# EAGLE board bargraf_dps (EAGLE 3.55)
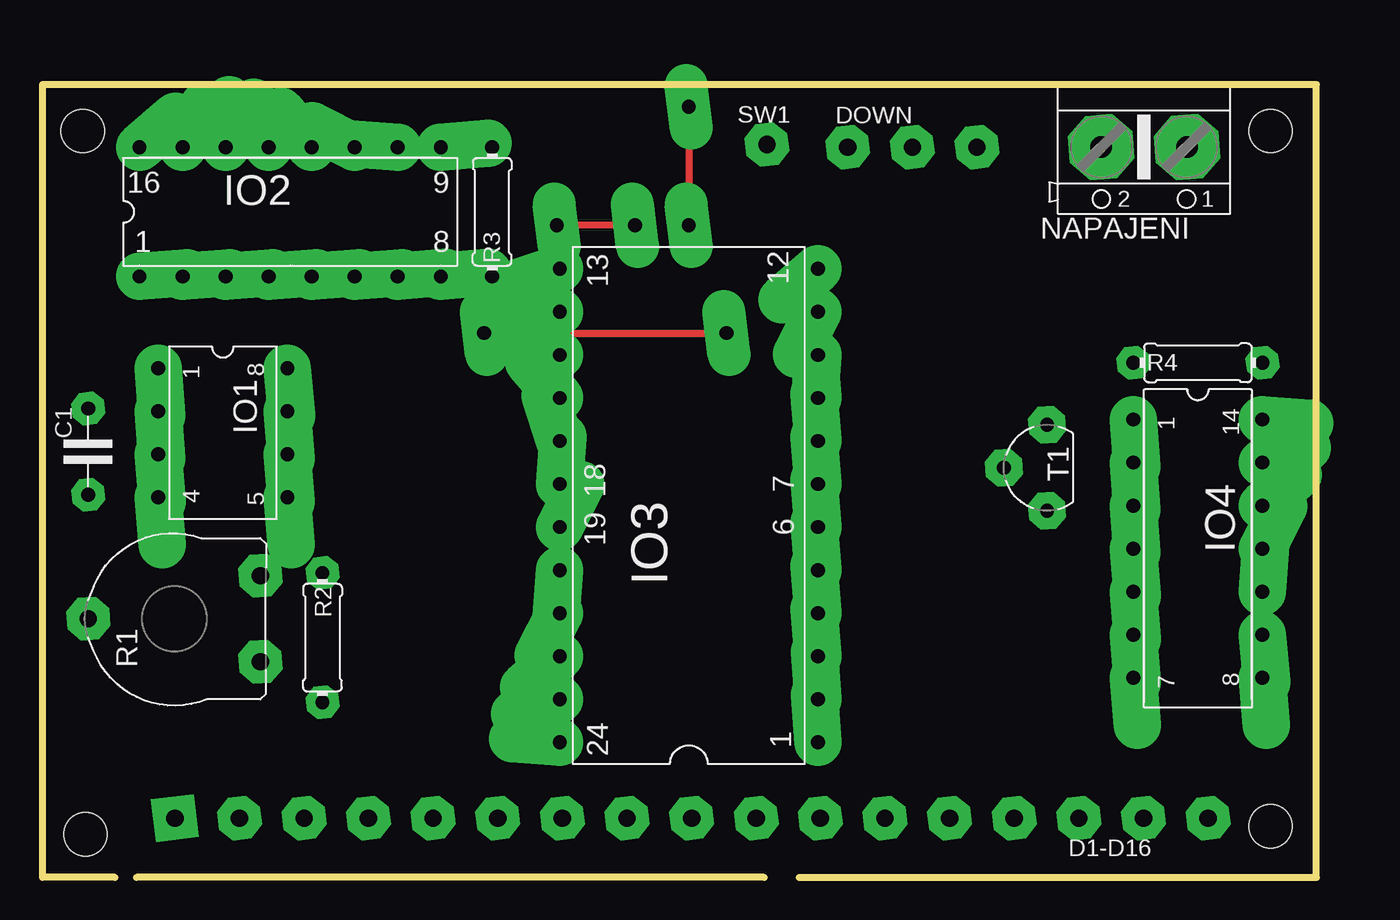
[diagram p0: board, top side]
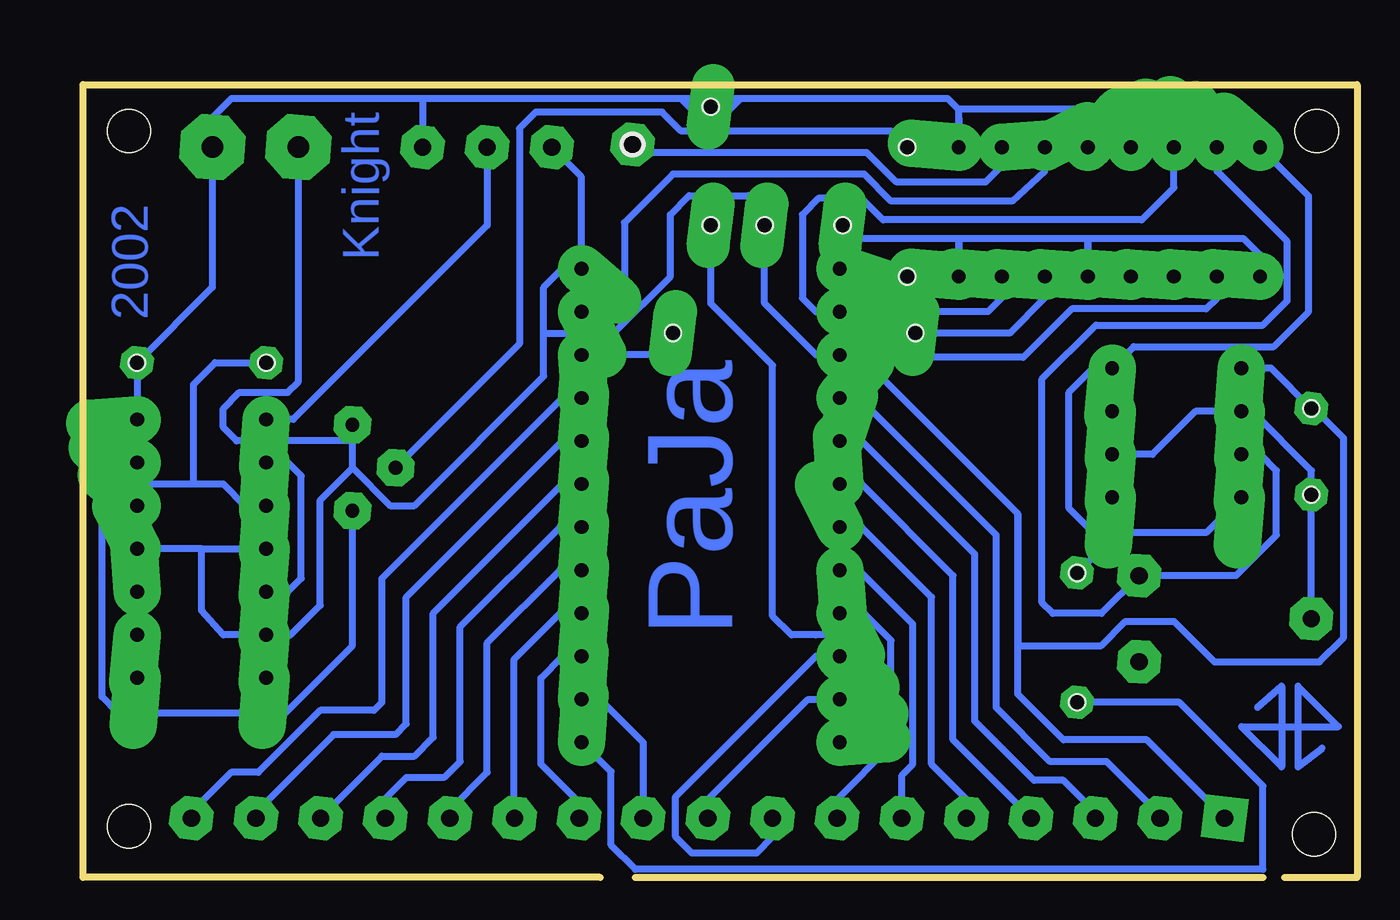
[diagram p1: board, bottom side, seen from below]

Size 75.21 x 46.78 mm. Coordinates in mm from the lower left corner, seen from the top.
Outline: 44.68,0 75.21,0 75.21,46.78 0,46.78 0,0 4.29,0
Outline: 42.61,0 5.57,0
Copper layers used: Top, Bottom
Holes 2.54 mm at 72.5,3.02 72.5,44.04 2.38,44.04 2.54,2.54

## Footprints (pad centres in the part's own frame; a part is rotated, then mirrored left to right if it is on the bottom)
5 = drill 0.813 pad 1.93 octagon:  -2.544,0;  2.544,0
D 16+1 = drill 1.016 pad 2.54 octagon: 0 7.62,0; 1 3.804,0; 2 19.068,0; 3 15.252,0; 4 11.436,0; 6 26.682,0; 7 22.866,0;  -26.682,0;  -30.498,0;  -19.05,0;  -22.866,0;  -7.602,0;  -11.418,0;  -15.234,0;  -0.012,0;  -3.828,0 | drill 1.016 pad 2.54 square: 5 30.498,0
D 3 = drill 1.016 pad 2.54 octagon:  -3.816,0;  0,0;  3.816,0
D 1-- = drill 0.813 pad 2.54 long:  0,0
L8 = drill 0.813 pad 2.8 offset:  -3.81,-3.81;  -1.27,-3.81;  1.27,-3.81;  3.81,-3.81;  3.81,3.81;  1.27,3.81;  -1.27,3.81;  -3.81,3.81
L16 = drill 0.813 pad 2.8 offset:  -8.89,-3.81;  -6.35,-3.81;  -3.81,-3.81;  -1.27,-3.81;  1.27,-3.81;  3.81,-3.81;  6.35,-3.81;  8.89,-3.81;  8.89,3.81;  6.35,3.81;  3.81,3.81;  1.27,3.81;  -1.27,3.81;  -3.81,3.81;  -6.35,3.81;  -8.89,3.81
L24 = drill 0.813 pad 2.8 offset:  -13.97,-7.62;  -11.43,-7.62;  -8.89,-7.62;  -6.35,-7.62;  -3.81,-7.62;  -1.27,-7.62;  1.27,-7.62;  3.81,-7.62;  6.35,-7.62;  8.89,-7.62;  11.43,-7.62;  13.97,-7.62;  13.97,7.62;  11.43,7.62;  8.89,7.62;  6.35,7.62;  3.81,7.62;  1.27,7.62;  -1.27,7.62;  -3.81,7.62;  -6.35,7.62;  -8.89,7.62;  -11.43,7.62;  -13.97,7.62
L14 = drill 0.813 pad 2.8 offset:  -7.62,-3.81;  -5.08,-3.81;  -2.54,-3.81;  0,-3.81;  2.54,-3.81;  5.08,-3.81;  7.62,-3.81;  7.62,3.81;  5.08,3.81;  2.54,3.81;  0,3.81;  -2.54,3.81;  -5.08,3.81;  -7.62,3.81
K500/2 = drill 1.27 pad 3.81 octagon:  -2.54,0;  2.54,0
10V = drill 1.016 pad 2.54 octagon:  -2.54,-5.08;  2.54,-5.08;  0,5.08
7,5 = drill 0.813 pad 1.93 octagon:  -3.816,0;  3.816,0
D 1 = drill 1.016 pad 2.54 octagon:  0,0
-92D = drill 0.813 pad 2.184 octagon:  0,-2.54;  2.54,0;  0,2.54

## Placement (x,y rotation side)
C1  100n  [5]  2.7,25.12 90 top
D1-D16  [D 16+1]  38.32,3.5 180 top
DOWN  2  [D 3]  51.36,43.09 0 top
E$1  [D 1--]  38.16,45.47 0 top
E$2  [D 1--]  26.08,32.12 0 top
E$3  [D 1--]  30.37,38.48 0 top
E$4  [D 1--]  34.98,38.48 0 top
E$5  [D 1--]  38.16,38.48 0 top
E$6  [D 1--]  40.39,32.12 0 top
E$7  [ 1]  3.98,8.9 0 top
IO1  7555  [L8]  10.65,26.23 270 top
IO2  4029  [L16]  14.63,39.27 0 top
IO3  4067  [L24]  38.16,21.94 90 top
IO4  4013  [L14]  68.21,19.4 270 top
NAPAJENI  [K500/2]  65.03,43.09 180 top
R1  1M  [10V]  7.79,15.26 90 top
R2  470  [7,5]  16.54,14.15 270 top
R3  10k  [7,5]  26.55,39.27 90 top
R4  1k2  [7,5]  68.21,30.37 0 top
SW1  [D 1]  42.77,43.25 0 top
T1  bc337  [-92D]  59.31,24.17 180 top

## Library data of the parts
C1 D1-D16 DOWN E$1-E$7 R2-R4 SW1 = 1_Paja1_
IO1-IO4 NAPAJENI R1 T1 = 1_PaJa_8

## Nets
S$1: DOWN. E$1. E$5. IO1. IO2. IO3. IO4. NAPAJENI. R2. R4.
S$2: IO3. R2.
S$3: IO4. R4. T1.
S$4: R3. T1.
S$5: IO2. R3.
S$6: D1-D16. IO3.
S$7: IO4.
S$8: C1. IO1. R1.
S$9: D1-D16. IO3.
S$10: IO1. IO2. R1.
S$11: C1. D1-D16.5 DOWN. E$3. E$4. IO1. IO2. IO3. IO4. NAPAJENI. T1.
S$12: IO2. IO3.
S$13: IO2. IO3.
S$14: IO2. IO3.
S$15: E$2. E$6. IO2. IO3.
S$16: IO2. SW1.
S$17: DOWN. IO4.
S$18: D1-D16. IO3.
S$19: D1-D16. IO3.
S$20: D1-D16. IO3.
S$21: D1-D16. IO3.
S$22: D1-D16. IO3.
S$23: D1-D16. IO3.
S$24: D1-D16. IO3.
S$25: D1-D16.1 IO3.
S$26: D1-D16.0 IO3.
S$27: D1-D16.4 IO3.
S$28: D1-D16.3 IO3.
S$29: D1-D16.2 IO3.
S$30: D1-D16.7 IO3.
S$31: D1-D16.6 IO3.

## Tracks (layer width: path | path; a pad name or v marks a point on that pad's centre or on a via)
S$1
  Top 0.406: E$1. E$5.
  Bottom 0.406: 23.52,43.08 23.52,44.38 23.53,45.32 | 23.53,45.32 6.68,45.32 5.72,44.36 5.72,43.41 5.74,43.39 IO2. 2.86,40.21 2.86,33.39 4.93,31.32 13.19,31.32 IO1. 15.59,30.04 17.01,28.62 17.01,21.78 15.58,20.35 15.42,20.35 | 6.84,22.42 8.9,20.35 15.42,20.35 | IO4. 72.02,27.5 72.03,27.51 R4. 67.58,34.82 67.58,43.09 67.57,43.09 67.58,43.12 67.58,44.84 66.46,45.95 55.17,45.95 | 16.54,17.97 15.42,19.08 15.42,20.35 | IO3. 29.39,7.97 28.62,8.75 28.62,13.52 29.41,14.31 | 29.41,14.31 31.96,14.31 | 29.41,14.31 33.39,14.31 34.5,15.42 34.5,30.21 38.16,33.87 E$5. | 36.41,45.95 39.91,45.95 | 39.91,45.95 55.17,45.95 | 23.53,45.32 24.17,45.95 36.41,45.95 | 23.53,45.32 23.53,43.57 | 36.41,45.95 38.16,45.95 E$1. | 36.41,45.95 37.21,45.16 | 39.91,45.95 39.11,45.16 | 55.17,45.95 DOWN.
S$2
  Bottom 0.406: 45.78,7.97 44.04,6.24 44.04,1.91 42.61,0.48 5.57,0.48 5.57,5.41 10.49,10.34 R2.
S$3
  Bottom 0.406: 64.4,21.94 64.55,21.94 65.67,21.94 66.94,23.21 68.69,23.21 | T1. 59.31,13.67 63.28,9.7 73.14,9.7 74.09,10.65 74.09,22.42 73.3,23.21 68.69,23.21 | 64.39,30.37 67.42,30.37 68.69,29.1 68.69,23.21
S$4
  Bottom 0.406: R3. 27.51,44.04 39.91,44.04 41.02,45.16 48.5,45.16 49.45,44.2 49.45,31.49 56.77,24.17
S$5
  Bottom 0.406: 20.98,35.46 20.99,35.45 20.99,34.19 21.78,33.39 25.44,33.39 26.55,34.5 26.55,35.46
S$6
  Bottom 0.406: 45.78,28.29 46.91,28.29 57.56,17.65 57.56,10.34 58.04,9.86 61.22,9.86 64.87,6.2 66.46,6.2 68.85,3.82 68.82,3.79 68.82,3.5
S$7
  Bottom 0.406: 64.4,24.48 63.12,24.48 62.33,23.69 62.33,17.65 63.12,16.85 64.08,16.85 64.08,16.86 64.4,16.86
S$8
  Bottom 0.406: R1. 2.71,15.42 2.7,15.42 2.7,22.58 2.7,24.01 6.2,27.5 6.84,27.5 9.54,27.5 12.08,24.96 14.46,24.96
S$9
  Bottom 0.406: 45.78,25.75 45.79,25.76 46.91,25.76 56.13,16.54 56.13,9.06 56.76,8.43 60.42,8.43 65.03,3.82 65,3.79 65,3.5
S$10
  Bottom 0.406: 6.84,24.96 5.72,24.96 4.77,24.01 4.77,20.19 7.16,17.81 12.87,17.81 12.87,17.8 15.09,15.58 17.97,15.58 18.6,16.22 18.6,29.41 15.42,32.59 5.57,32.59 4.13,34.03 4.13,37.52 8.27,41.66 8.27,43.07 8.28,43.08
S$11
  Top 0.406: E$4. E$3.
  Bottom 0.406: 68.21,19.4 68.21,15.74 66.94,14.31 64.55,14.31 64.55,14.32 64.4,14.32 | 64.4,11.78 64.4,11.92 64.39,11.93 64.4,11.93 64.4,14.32 | 68.21,19.4 64.4,19.4 | 68.21,19.4 72.02,19.4 | 5.74,35.46 5.74,36.74 6.68,37.68 15.9,37.68 15.9,35.46 15.9,37.68 23.53,37.68 | 23.53,37.68 23.53,35.93 23.52,35.92 23.52,35.46 23.52,37.68 23.53,37.68 | 6.84,30.04 5.08,30.04 C1. 2.54,27.67 0.79,25.92 0.79,14.15 2.23,12.72 8.43,12.72 10.81,15.11 13.67,15.11 15.11,13.67 20.03,13.67 20.03,21.46 | D1-D16.5 7.79,3.53 7.79,3.5 12.4,8.11 17.33,8.11 20.03,10.81 20.03,21.46 | 20.03,21.46 29.41,30.85 29.57,30.85 29.59,30.83 30.54,30.83 31.94,30.83 34.98,33.87 E$4. 34.98,39.27 35.93,40.23 39.43,40.23 40.55,39.11 40.55,35.46 43.88,32.12 48.02,32.12 | 64.08,14.31 62.96,14.31 61.22,16.06 61.22,22.26 59.31,24.17 | 23.53,37.68 29.57,37.68 E$3. | 48.02,32.12 48.02,34.82 46.93,35.91 45.78,35.91 45.79,35.92 45.79,41.34 47.54,43.09 | 48.02,32.12 48.02,29.57 55.65,21.94 57.08,21.94 59.31,24.17 | 59.31,25.76 59.31,26.71 | 59.31,25.76 66.14,25.76 66.94,26.55 66.94,27.67 65.98,28.62 63.12,28.62 62.49,29.26 62.49,43.06 NAPAJENI. | 64.08,14.31 64.24,14.31 | 64.4,14.32 64.09,14.32 64.08,14.31 | 59.31,24.17 59.31,25.76
S$12
  Bottom 0.406: 8.28,35.46 8.27,35.29 8.27,34.19 8.9,33.55 16.85,33.55 19.72,30.69 27.19,30.69 28.14,31.64 28.14,34.5 29.57,35.93 29.57,35.91 30.54,35.91
S$13
  Bottom 0.406: 30.54,33.37 31.94,33.37 32.75,34.19 32.75,39.11 31.8,40.07 29.26,40.07 27.98,38.8 12.72,38.8 10.82,40.7 10.82,43.08
S$14
  Bottom 0.406: 18.44,43.08 18.44,41.66 20.35,39.91 27.51,39.91 29.1,41.5 40.39,41.5 43.25,38.64 43.25,34.66 44.54,33.37 45.78,33.37
S$15
  Top 0.406: E$2. E$6.
  Bottom 0.406: 18.44,35.46 18.44,34.19 20.51,32.12 E$2. | 45.78,30.83 45.77,30.85 41.66,30.85 E$6.
S$16
  Bottom 0.406: 20.98,43.08 20.98,41.99 21.94,41.02 27.19,41.02 28.94,42.77 42.29,42.77 SW1.
S$17
  Bottom 0.406: 64.4,27.02 64.22,27.02 64.08,27.03 62.8,27.03 51.36,38.48 51.36,43.09
S$18
  Bottom 0.406: 45.78,23.21 46.91,23.21 54.54,15.58 54.54,8.27 55.65,7.16 57.56,7.16 60.9,3.82 61.06,3.82 61.06,3.63 61.19,3.5
S$19
  Bottom 0.406: 45.78,20.67 47.06,20.67 52.95,14.79 52.95,6.84 53.9,5.88 56.13,5.88 57.4,4.61 57.4,3.53 57.37,3.5
S$20
  Bottom 0.406: 45.78,18.13 45.79,18.13 47.06,18.13 51.36,13.83 51.36,6.2 53.58,3.98 53.58,3.53 53.55,3.5
S$21
  Bottom 0.406: 45.78,15.59 45.79,15.58 47.06,15.58 49.77,12.88 49.77,3.53 49.74,3.5
S$22
  Bottom 0.406: 45.78,13.05 45.79,13.04 46.91,13.04 48.18,11.77 48.18,6.68 45.95,4.45 45.95,3.53 45.92,3.5
S$23
  Bottom 0.406: 45.78,10.51 44.7,10.51 42.14,7.95 42.14,3.51 D1-D16.
S$24
  Bottom 0.406: 30.54,10.51 32.42,10.51 38.32,4.61 38.32,3.66 38.33,3.65 38.33,3.5
S$25
  Bottom 0.406: 30.54,13.05 31.94,13.05 40.23,4.77 40.23,2.38 39.27,1.43 35.46,1.43 34.5,2.38 34.5,3.49 D1-D16.1
S$26
  Bottom 0.406: 30.54,15.59 29.11,15.59 27.51,13.99 27.51,7.79 30.69,4.61 30.69,3.82 30.7,3.8 D1-D16.0
S$27
  Bottom 0.406: 30.54,18.13 30.53,18.13 29.41,18.13 26.23,14.95 26.23,6.68 26.87,6.04 D1-D16.4
S$28
  Bottom 0.406: 30.54,20.67 29.26,20.67 25.12,16.54 25.12,6.68 23.05,4.61 D1-D16.3
S$29
  Bottom 0.406: 30.54,23.21 29.26,23.21 23.85,17.81 23.85,8.11 19.24,3.5 D1-D16.2
S$30
  Bottom 0.406: 30.54,25.75 29.26,25.75 29.26,25.76 22.58,19.08 22.58,9.22 19.08,5.72 17.33,5.72 15.42,3.82 15.42,3.53 D1-D16.7
S$31
  Bottom 0.406: 30.54,28.29 30.53,28.3 29.41,28.3 21.31,20.19 21.31,10.02 18.13,6.84 14.79,6.84 11.61,3.66 11.64,3.63 D1-D16.6

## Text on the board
Bottom: Knight | 2002 | PaJa
tValues: - | +6V | 1 | - | 16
